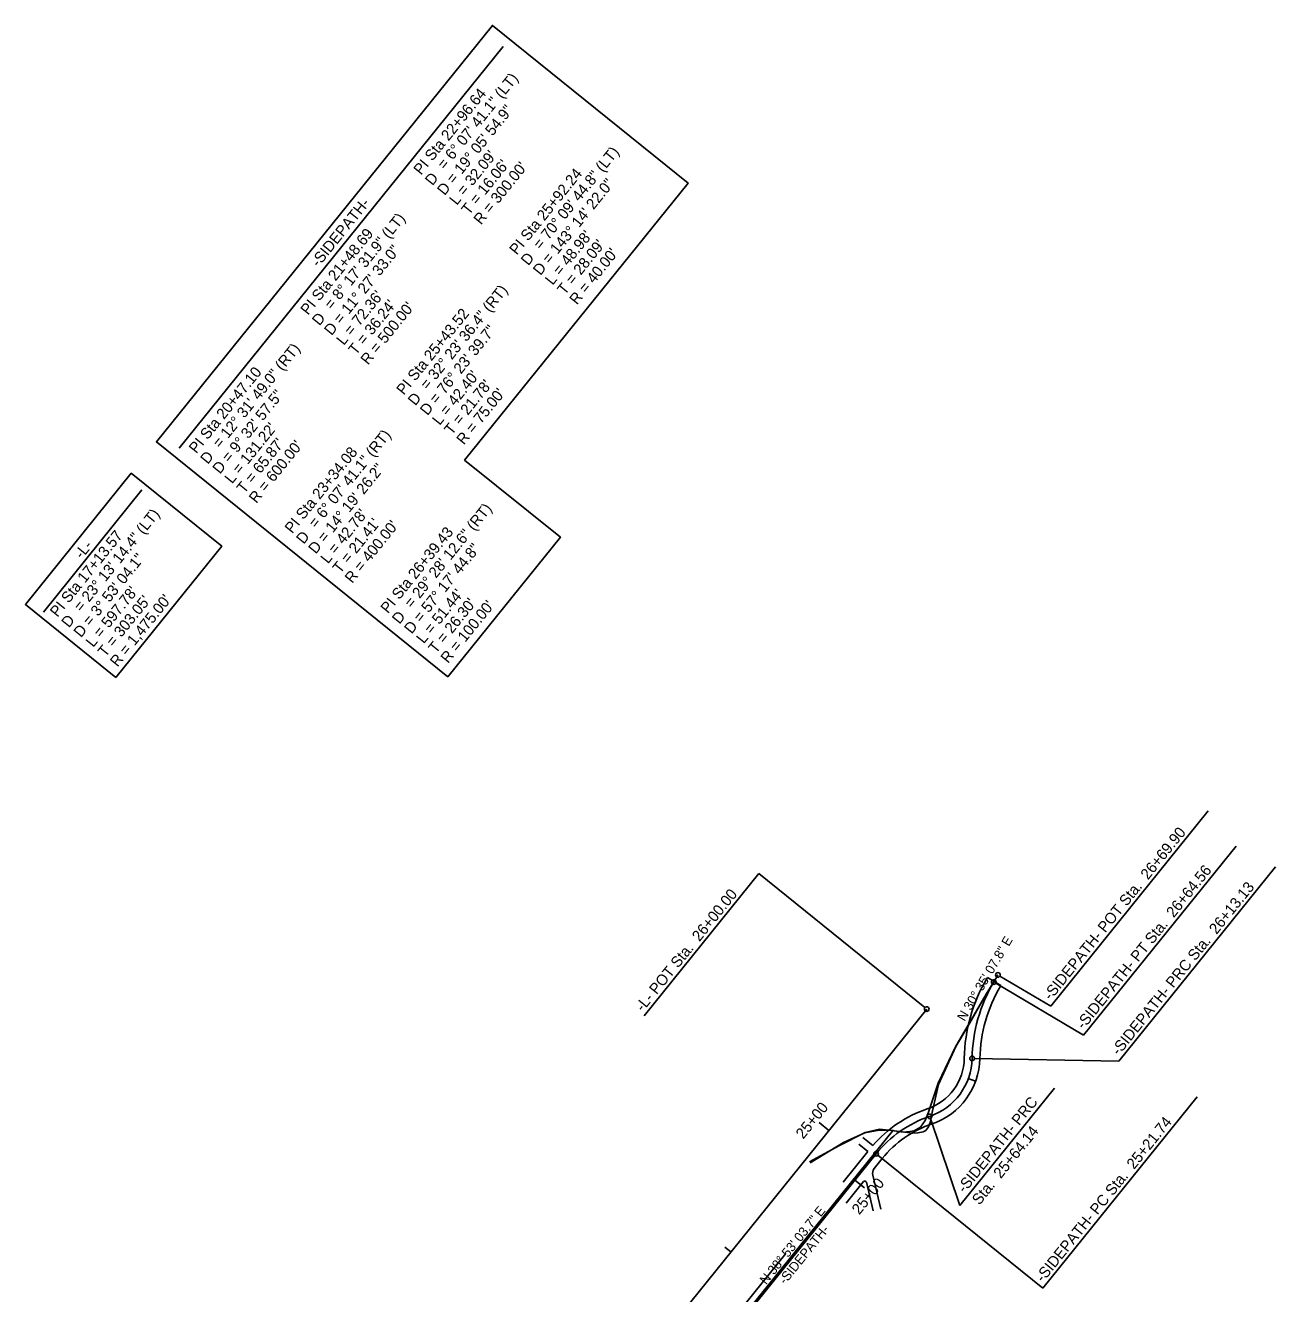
# Model space of a CAD drawing. Extents: x 1487048 to 1489168, y 497704 to 500108.
# Drawn here: x 1488367 to 1489168, y 499192 to 500005 of the extents above; entities that cross this region are included whole.
import ezdxf

# ---------------------------------------------------------------- set-up
doc = ezdxf.new("R2010")
doc.units = 0
for name, color, linetype in [('Prop Conc 4in Sidewalk', 7, 'Continuous'), ('Prop Grid Mask', 7, 'Continuous'), ('Prop Horizontal Alignment', 7, 'Continuous'), ('Prop Horizontal Alignment Curve and Spiral Data', 7, 'Continuous'), ('Prop Horizontal Alignment Direction Label', 7, 'Continuous'), ('Prop Horizontal Alignment Station Label', 7, 'Continuous'), ('Prop Horizontal Alignment Tick Label', 7, 'Continuous'), ('Prop Horizontal Alignment Tick Large', 7, 'Continuous'), ('Prop Horizontal Alignment Tick Small', 7, 'Continuous'), ('Scratch_Level_3', 7, 'Continuous'), ('Scratch_Level_5', 7, 'Continuous')]:
    doc.layers.add(name, color=color, linetype=linetype)

msp = doc.modelspace()

# ---------------------------------------------------------------- linework, layer by layer
at = {"layer": 'Prop Conc 4in Sidewalk'}
for p, q in [((1488983.22, 499394.23), (1488983.44, 499394.61)), ((1488992.05, 499389.52), (1488983.44, 499394.61)), ((1488991.83, 499389.14), (1488992.05, 499389.52)), ((1488910, 499286.97), (1488903.58, 499292.15)), ((1488891.01, 499263.42), (1488906.86, 499283.08)), ((1488906.86, 499283.08), (1488901.02, 499287.79)), ((1488910.92, 499272.19), (1488916.06, 499278.56)), ((1488892.95, 499249.9), (1488904.15, 499263.79)), ((1488915.22, 499246.16), (1488909.96, 499267.88)), ((1488910.36, 499244.98), (1488905.9, 499263.4)), ((1488803.89, 499155.39), (1488854.19, 499217.78)), ((1488807.78, 499152.26), (1488861.05, 499218.32))]:
    msp.add_line(p, q, dxfattribs=at)
for centre, radius, start, end in [((1489073.61, 499340.81), 105, 149.4145, 178.88465), ((1489073.61, 499340.81), 95, 149.4145, 178.88465), ((1488933.64, 499343.53), 35, 288.72221, 358.88465), ((1488933.64, 499343.53), 45, 288.72221, 358.88465), ((1488970.55, 499234.62), 80, 108.72221, 139.14744), ((1488970.55, 499234.62), 70, 108.72221, 141.11565), ((1488914.82, 499269.05), 5, 141.11565, 193.61448), ((1488904.93, 499263.16), 1, 13.61448, 141.11565)]:
    msp.add_arc(centre, radius, start, end, dxfattribs=at)
at = {"layer": 'Prop Grid Mask'}
for points in [[(1488637.62, 499587.32), (1488709.77, 499676.79), (1488648.44, 499726.25), (1488791.65, 499903.83), (1488666.26, 500004.94), (1488450.9, 499737.9)], [(1488424.93, 499586.95), (1488492.8, 499671.1), (1488434.77, 499717.9), (1488366.91, 499633.74)]]:
    msp.add_lwpolyline(points, close=True, dxfattribs=at)
at = {"layer": 'Prop Horizontal Alignment'}
for p, q in [((1488987.52, 499391.69), (1488990.24, 499396.28)), ((1488573.13, 498913.85), (1488944.57, 499374.44)), ((1488807.78, 499152.26), (1488912.17, 499281.7))]:
    msp.add_line(p, q, dxfattribs=at)
for centre, radius, start, end in [((1489073.61, 499340.81), 100, 149.4145, 178.88465), ((1488933.64, 499343.53), 40, 288.72221, 358.88465), ((1488970.55, 499234.62), 75, 108.72221, 141.11565)]:
    msp.add_arc(centre, radius, start, end, dxfattribs=at)
at = {"layer": 'Prop Horizontal Alignment Curve and Spiral Data'}
for p, q in [((1488465.57, 499733.98), (1488673.19, 499991.43)), ((1488378.43, 499628.91), (1488441.54, 499707.17))]:
    msp.add_line(p, q, dxfattribs=at)
at = {"layer": 'Prop Horizontal Alignment Station Label'}
for p, q in [((1489125.02, 499501.54), (1489024.03, 499376.31)), ((1489142.8, 499478.87), (1489045.06, 499357.68)), ((1488763.5, 499370.15), (1488836.95, 499461.23)), ((1488943.4, 499375.38), (1488836.95, 499461.23)), ((1489168.19, 499465.64), (1489067.61, 499340.92)), ((1488991.53, 499395.52), (1489024.03, 499376.31)), ((1488988.81, 499390.92), (1489045.06, 499357.68)), ((1488975.13, 499342.72), (1489067.61, 499340.92)), ((1488965.85, 499248.49), (1489026.53, 499323.73)), ((1489117.92, 499318.2), (1489019, 499195.54)), ((1488946.96, 499304.23), (1488965.85, 499248.49)), ((1488913.33, 499280.76), (1489019, 499195.54))]:
    msp.add_line(p, q, dxfattribs=at)
for centre in [(1488990.24, 499396.28), (1488987.52, 499391.69), (1488944.57, 499374.44), (1488973.63, 499342.75), (1488946.47, 499305.65), (1488912.17, 499281.7)]:
    msp.add_circle(centre, 1.5, dxfattribs=at)
at = {"layer": 'Prop Horizontal Alignment Tick Large'}
for p, q in [((1488881.79, 499296.6), (1488875.56, 499301.62)), ((1488898.52, 499264.77), (1488904.75, 499259.75))]:
    msp.add_line(p, q, dxfattribs=at)
at = {"layer": 'Prop Horizontal Alignment Tick Small'}
for p, q in [((1488971.24, 499329.91), (1488975.94, 499328.2)), ((1488819.02, 499218.76), (1488815.12, 499221.9))]:
    msp.add_line(p, q, dxfattribs=at)
at = {"layer": 'Scratch_Level_3'}
msp.add_lwpolyline([(1488869.55, 499276.53), (1488888.17, 499286.85), (1488905.19, 499295.29), (1488914.4, 499297.42), (1488922.13, 499296.59), (1488935.54, 499294.92), (1488938.98, 499295.06), (1488942.3, 499295.65), (1488943.95, 499296.66), (1488945.75, 499298.95), (1488946.91, 499302.38), (1488948.31, 499309.23), (1488952.17, 499326.08), (1488963.21, 499350.47), (1488970.45, 499362.67), (1488982.74, 499383.91), (1488989.88, 499395.67)], dxfattribs=at)
at = {"layer": 'Scratch_Level_5'}
msp.add_line((1488808.61, 499154.89), (1488923.23, 499297.01), dxfattribs=at)
msp.add_lwpolyline([(1488869.97, 499275.93), (1488891.34, 499288.83), (1488904.83, 499295.05), (1488914.18, 499296.75), (1488922.26, 499296.53), (1488929.41, 499295.46), (1488933.79, 499295.96), (1488936.46, 499296.41), (1488940.58, 499298.81), (1488943.62, 499302.98), (1488945.72, 499308.31), (1488951.95, 499326.9), (1488963.18, 499350.61), (1488971.18, 499364.18), (1488982.78, 499384.01), (1488988.2, 499392.9)], dxfattribs=at)

# ---------------------------------------------------------------- texts
at = {"layer": 'Prop Horizontal Alignment Curve and Spiral Data'}
for s, p in [('= 6%%d 07\' 41.1" (LT)', (1488635.67, 499911.98)), ('PI Sta 22+96.64', (1488620.48, 499908.59)), ('D = 19%%d 05\' 54.9"', (1488635.62, 499895.51)), ("L = 32.09'", (1488643.41, 499889.23)), ('= 70%%d 09\' 44.8" (LT)', (1488697.1, 499860.71)), ("T = 16.06'", (1488651.19, 499882.96)), ("R = 300.00'", (1488658.97, 499876.68)), ('D', (1488627.84, 499901.79)), ('PI Sta 25+92.24', (1488681.9, 499857.32)), ('D = 143%%d 14\' 22.0"', (1488697.05, 499844.24)), ('-SIDEPATH-', (1488554.71, 499849.5)), ('= 8%%d 17\' 31.9" (LT)', (1488563.26, 499822.18)), ('PI Sta 21+48.69', (1488548.06, 499818.8)), ("L = 48.98'", (1488704.83, 499837.97)), ("T = 28.09'", (1488712.62, 499831.69)), ('D = 11%%d 27\' 33.0"', (1488563.21, 499805.72)), ('D', (1488689.26, 499850.52)), ("R = 40.00'", (1488720.4, 499825.41)), ("L = 72.36'", (1488570.99, 499799.44)), ('= 32%%d 23\' 36.4" (RT)', (1488624.69, 499770.91)), ("T = 36.24'", (1488578.77, 499793.16)), ("R = 500.00'", (1488586.56, 499786.88)), ('D', (1488555.42, 499811.99)), ('PI Sta 25+43.52', (1488609.49, 499767.53)), ('D = 76%%d 23\' 39.7"', (1488624.63, 499754.45)), ('= 12%%d 31\' 49.0" (RT)', (1488491.69, 499733.43)), ('PI Sta 20+47.10', (1488476.49, 499730.04)), ("L = 42.40'", (1488632.42, 499748.17)), ("T = 21.78'", (1488640.2, 499741.89)), ('D = 9%%d 32\' 57.5"', (1488491.63, 499716.96)), ('D', (1488616.85, 499760.72)), ("R = 75.00'", (1488647.99, 499735.61)), ("L = 131.22'", (1488499.42, 499710.69)), ('= 6%%d 07\' 41.1" (RT)', (1488553.11, 499682.16)), ("T = 65.87'", (1488507.2, 499704.41)), ("R = 600.00'", (1488514.98, 499698.13)), ('D', (1488483.85, 499723.24)), ('PI Sta 23+34.08', (1488537.91, 499678.77)), ('D = 14%%d 19\' 26.2"', (1488553.06, 499665.69)), ("L = 42.78'", (1488560.84, 499659.42)), ('= 29%%d 28\' 12.6" (RT)', (1488614.54, 499630.89)), ('= 23%%d 13\' 14.4" (LT)', (1488402.66, 499628.58)), ("T = 21.41'", (1488568.63, 499653.14)), ("R = 400.00'", (1488576.41, 499646.86)), ('PI Sta 17+13.57', (1488387.46, 499625.19)), ('D', (1488545.28, 499671.97)), ('PI Sta 26+39.43', (1488599.34, 499627.5)), ('-L-', (1488403.13, 499662.47)), ('D = 57%%d 17\' 44.8"', (1488614.49, 499614.43)), ('D = 3%%d 53\' 04.1"', (1488402.6, 499612.11)), ("L = 597.78'", (1488410.39, 499605.84)), ("T = 303.05'", (1488418.17, 499599.56)), ("R = 1,475.00'", (1488425.96, 499593.28)), ("L = 51.44'", (1488622.27, 499608.15)), ("T = 26.30'", (1488630.05, 499601.87)), ("R = 100.00'", (1488637.84, 499595.59)), ('D', (1488394.82, 499618.39)), ('D', (1488606.7, 499620.7))]:
    msp.add_text(s, height=7, rotation=51.11565, dxfattribs=at).set_placement(p)
at = {"layer": 'Prop Horizontal Alignment Direction Label'}
for s, rotation, p in [('N 30%%d 35\' 07.8" E', 59.4145, (1488968.84, 499366.17)), ('N 38%%d 53\' 03.7" E', 51.11565, (1488841.65, 499197.42)), ('-SIDEPATH-', 51.11565, (1488853.85, 499197.49))]:
    msp.add_text(s, height=6, rotation=rotation, dxfattribs=at).set_placement(p)
at = {"layer": 'Prop Horizontal Alignment Station Label'}
for s, p in [('-SIDEPATH- POT Sta.  26+69.90', (1489024.06, 499379.54)), ('-SIDEPATH- PT Sta.  26+64.56', (1489045.1, 499360.91)), ('-L- POT Sta.  26+00.00', (1488762.7, 499372.34)), ('-SIDEPATH- PRC Sta.  26+13.13', (1489067.64, 499344.15)), ('-SIDEPATH- PRC', (1488968.84, 499256.03)), ('-SIDEPATH- PC Sta.  25+21.74', (1489019.04, 499198.77)), ('Sta.  25+64.14', (1488978.37, 499248.34))]:
    msp.add_text(s, height=7, rotation=51.11565, dxfattribs=at).set_placement(p)
at = {"layer": 'Prop Horizontal Alignment Tick Label'}
for p in [(1488865.44, 499290.67), (1488901.36, 499242.15)]:
    msp.add_text('25+00', height=7, rotation=51.11565, dxfattribs=at).set_placement(p)

doc.saveas('drawing.dxf')
